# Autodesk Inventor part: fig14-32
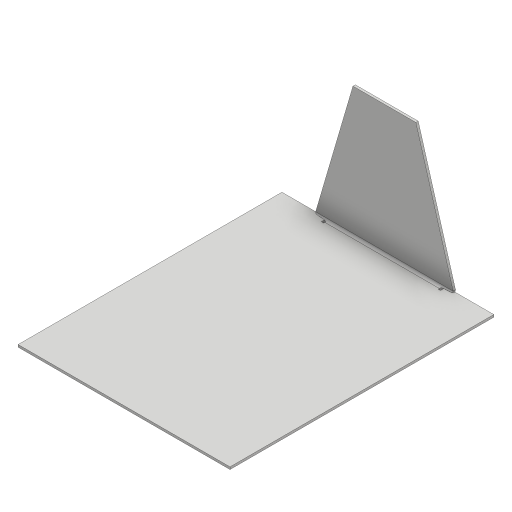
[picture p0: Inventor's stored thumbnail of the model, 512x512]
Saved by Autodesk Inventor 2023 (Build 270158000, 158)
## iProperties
Created: 2017-05
Part Number: fig14-32
Material: Generic
Document SubType Name: Sheet Metal
Designer: CADCIM 00
Density: 1 g/cm^3
Sheet Metal Rule: Default_mm
Appearance: Default
Author: CADCIM 00
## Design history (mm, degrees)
node "Face1"
  sketch "Sketch1"
    geometry: L1 (0, 0)-(45.552, 0); L2 (45.552, 0)-(45.552, 56.721); L3 (45.552, 56.721)-(0, 56.721); L4 (0, 56.721)-(0, 0)
    constraints: 8 end point, 2 parallel, 1 horizontal, 1 perpendicular
node "Face2"
  sketch "Sketch2"
    geometry: L1 (10.232, -9.455)-(15.772, -28.394); L2 (15.772, -28.394)-(29.3, -28.394); L3 (29.3, -28.394)-(34.84, -9.455); L4 (34.84, -9.455)-(10.232, -9.455); 1 further point
    constraints: 8 end point, 1 horizontal, 1 parallel
body "Solid1"
face "Plate1" dims "d0" = 0.5 (= Thickness)
face "Plate2" dims "d0" = 0.5 (= Thickness), "d1" = 0.5 (= BendRadius), "d2" = 0.5 (= BendReliefWidth), "d4" = 1 (= MinimumRemnant)
bend "Bend1" dims "d0" = 0.5 (= Thickness), "d1" = 0.5 (= BendRadius), "d2" = 0.5 (= BendReliefWidth), "d3" = 0.25 (= BendReliefDepth), "d4" = 1 (= MinimumRemnant), "d5" = 0.5 (= TransitionRadius), "SeamGap" = 0.01
other parameters: "Thickness" = 0.5, "BendRadius" = 0.5 (= Thickness), "BendReliefWidth" = 0.5 (= Thickness), "BendReliefDepth" = 0.25 (= 0.5 x Thickness), "CornerReliefSize" = 2 (= 4 x Thickness), "MinimumRemnant" = 1 (= 2 x Thickness), "TransitionRadius" = 0.5 (= BendRadius), "JacobiRadiusSize" = 0.5 (= BendRadius), "GapSize" = 0.5 (= Thickness)
